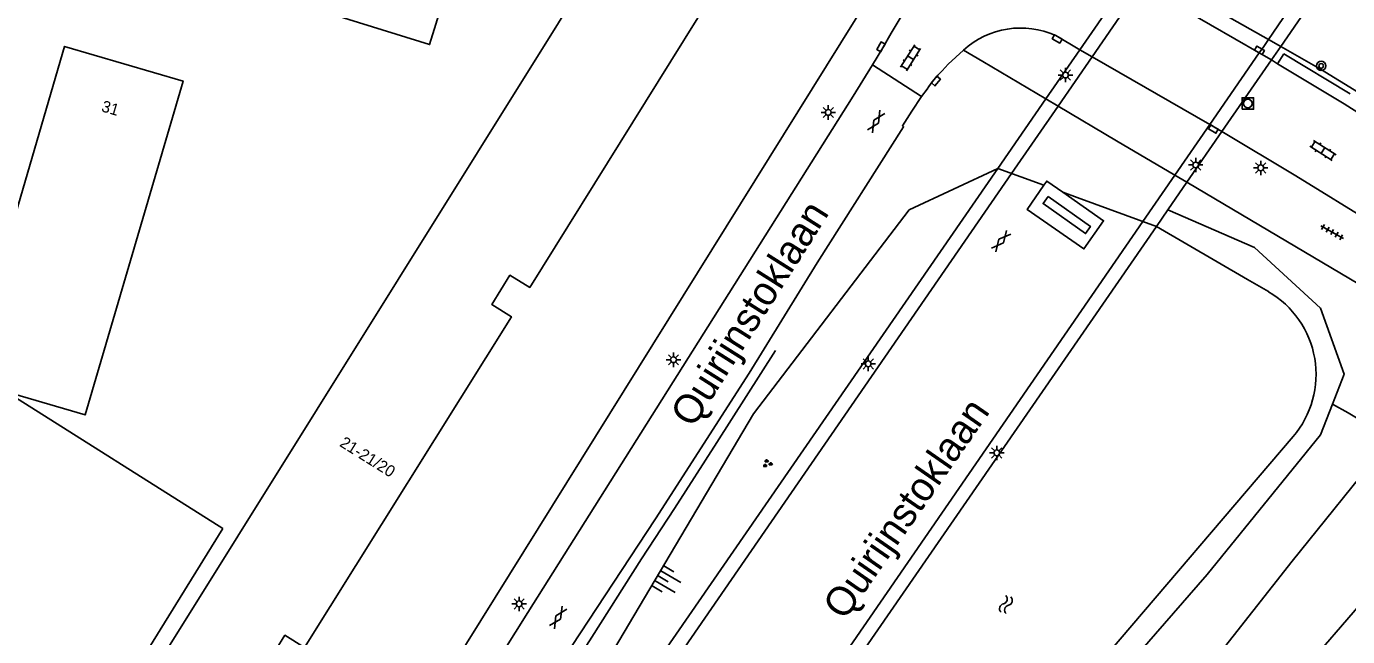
# Model space of a CAD drawing. Extents: x 132999 to 136000, y 398499 to 400501.
# Drawn here: x 134331.8 to 134446.1, y 398769 to 398821.9 of the extents above; entities that cross this region are included whole.
import ezdxf

# ---------------------------------------------------------------- set-up
doc = ezdxf.new("R2010")
doc.units = 0
for name, color, linetype in [('gg-afsc-hekwerk', 7, 'Continuous'), ('gg-anno-huisnummerreeks BGT', 7, 'Continuous'), ('gg-anno-openbare ruimte label', 7, 'Continuous'), ('gg-bbg-gedigitaliseerde bebouwing', 7, 'Continuous'), ('gg-bbg-gedigitaliseerde bijgebouw', 7, 'Continuous'), ('gg-bbg-hoofdgebouw', 7, 'Continuous'), ('gg-knt-BGT kruinlijn', 7, 'Continuous'), ('gg-knt-bovenkant onderkant talud', 7, 'Continuous'), ('gg-knt-bronhoudergrens', 7, 'Continuous'), ('gg-knt-verharding', 7, 'Continuous'), ('gg-knt-verharding nz', 7, 'Continuous'), ('gg-kwrk-kunstwerk', 7, 'Continuous'), ('gg-kwrk-kunstwerk niveau 01', 7, 'Continuous'), ('gt-grn-groengrens', 7, 'Continuous'), ('gt-knt-geleideconstructie', 7, 'Continuous'), ('gt-symb-boom', 7, 'Continuous'), ('gt-symb-gesloten verharding', 7, 'Continuous'), ('gt-symb-groenvak', 7, 'Continuous'), ('gt-symb-klinker verharding', 7, 'Continuous'), ('gt-symb-kolk', 7, 'Continuous'), ('gt-symb-lichtmast', 7, 'Continuous'), ('gt-symb-rioolschacht', 7, 'Continuous'), ('gt-symb-talud symbool', 7, 'Continuous'), ('gt-symb-tegel verharding', 7, 'Continuous'), ('gt-symb-watersymbool', 7, 'Continuous')]:
    doc.layers.add(name, color=color, linetype=linetype)

# ---------------------------------------------------------------- blocks, each defined once
blk = doc.blocks.new('gt0-TEG1')
at = {"layer": 'gt-symb-tegel verharding'}
for p, q in [((-1.12, 0), (1.12, 0)), ((-0.9, -0.25), (-0.9, 0.25)), ((-0.45, -0.25), (-0.45, 0.25)), ((0, -0.25), (0, 0.25)), ((0.45, -0.25), (0.45, 0.25)), ((0.9, -0.25), (0.9, 0.25))]:
    blk.add_line(p, q, dxfattribs=at)
blk = doc.blocks.new('gt0-LMAST')
at = {"layer": 'gt-symb-lichtmast'}
for p, q in [((-0.18, 0.17), (-0.45, 0.44)), ((-0.01, 0.25), (-0.01, 0.62)), ((0.17, 0.17), (0.44, 0.44)), ((-0.26, 0), (-0.63, 0)), ((-0.18, -0.18), (-0.45, -0.45)), ((-0.01, -0.25), (-0.01, -0.63)), ((0.44, -0.45), (0.17, -0.18)), ((0.24, 0), (0.62, 0))]:
    blk.add_line(p, q, dxfattribs=at)
blk.add_circle((-0.01, 0), 0.25, dxfattribs=at)
blk = doc.blocks.new('gt0-KL1')
at = {"layer": 'gt-symb-klinker verharding'}
for p, q in [((-1.15, 0.3), (1.15, 0.3)), ((-1, -0.3), (-1, 0.3)), ((-0.5, 0.3), (-0.5, 0.45)), ((0, -0.3), (0, 0.3)), ((0.5, 0.3), (0.5, 0.45)), ((1, -0.3), (1, 0.3)), ((-1.15, -0.3), (1.15, -0.3)), ((-0.5, -0.45), (-0.5, -0.3)), ((0.5, -0.45), (0.5, -0.3))]:
    blk.add_line(p, q, dxfattribs=at)
blk = doc.blocks.new('gt0-BOOM')
at = {"layer": 'gt-symb-boom'}
for radius in [0.4, 0.2]:
    blk.add_circle((0, 0), radius, dxfattribs=at)
blk = doc.blocks.new('gt0-KOLK')
at = {"layer": 'gt-symb-kolk'}
blk.add_lwpolyline([(0, 0), (0.37, 0), (0.37, 0.4), (-0.38, 0.4), (-0.38, 0), (0, 0)], dxfattribs=at)
blk = doc.blocks.new('gt0-GESVH1')
at = {"layer": 'gt-symb-gesloten verharding'}
for p, q in [((-0.99, -0.26), (0.01, 0.24)), ((0.01, -0.26), (-0.99, 0.24)), ((0.01, 0.24), (1.01, -0.26)), ((1.01, 0.24), (0.01, -0.26))]:
    blk.add_line(p, q, dxfattribs=at)
blk = doc.blocks.new('gt0-RS')
at = {"layer": 'gt-symb-rioolschacht'}
blk.add_lwpolyline([(-0.5, -0.5), (0.5, -0.5), (0.5, 0.5), (-0.5, 0.5)], close=True, dxfattribs=at)
blk.add_circle((0, 0), 0.375, dxfattribs=at)
blk = doc.blocks.new('gt0-WA')
at = {"layer": 'gt-symb-watersymbool'}
for centre, start, end in [((-0.32, 0.02), 28.0725, 151.9275), ((0.43, 0.42), 208.0725, 331.9275), ((-0.32, -0.43), 28.0725, 151.9275), ((0.43, -0.03), 208.0725, 331.9275)]:
    blk.add_arc(centre, 0.425, start, end, dxfattribs=at)
blk = doc.blocks.new('gt0-TALUD_1')
at = {"layer": 'gt-symb-talud symbool'}
for p, q in [((-1, -1), (-1, 0)), ((-0.5, -2), (-0.5, 0)), ((0, -1), (0, 0)), ((0.5, -2), (0.5, 0)), ((1, -1), (1, 0))]:
    blk.add_line(p, q, dxfattribs=at)
blk = doc.blocks.new('gt0-GRVAK')
at = {"layer": 'gt-symb-groenvak'}
for p, q in [((-0.11, 0.19), (-0.23, 0.24)), ((-0.18, 0.15), (0.09, 0.15)), ((-0.09, 0.21), (-0.16, 0.32)), ((-0.05, 0.21), (-0.05, 0.39)), ((0, 0.21), (0.06, 0.32)), ((0.01, 0.19), (0.13, 0.24)), ((0.26, -0.05), (0.2, 0.06)), ((0.3, -0.05), (0.3, 0.13)), ((0.35, -0.05), (0.41, 0.06)), ((-0.24, -0.23), (-0.36, -0.18)), ((-0.32, -0.26), (-0.05, -0.26)), ((-0.23, -0.21), (-0.29, -0.09)), ((-0.18, -0.2), (-0.18, -0.02)), ((-0.14, -0.21), (-0.07, -0.09)), ((-0.12, -0.23), (0, -0.18)), ((0.24, -0.07), (0.12, -0.02)), ((0.17, -0.11), (0.44, -0.11)), ((0.37, -0.07), (0.49, -0.02))]:
    blk.add_line(p, q, dxfattribs=at)

msp = doc.modelspace()

# ---------------------------------------------------------------- linework, layer by layer
at = {"layer": 'gg-afsc-hekwerk'}
for p, q in [((134362.12, 398755.98), (134404.98, 398824.83)), ((134419.99, 398815.58), (134414.54, 398818.81)), ((134421.05, 398814.96), (134419.99, 398815.58)), ((134426.1, 398811.96), (134421.05, 398814.96)), ((134431.15, 398808.97), (134426.1, 398811.96)), ((134432.19, 398808.36), (134431.15, 398808.97)), ((134453.08, 398795.98), (134432.19, 398808.36))]:
    msp.add_line(p, q, dxfattribs=at)
at = {"layer": 'gg-bbg-gedigitaliseerde bebouwing'}
for p in [(134330.09, 398790.22), (134307.47, 398711.69)]:
    msp.add_line(p, (134348.81, 398778.38), dxfattribs=at)
msp.add_lwpolyline([(134326.65, 398791.23), (134335.11, 398820.12), (134345.36, 398817.12), (134336.9, 398788.22), (134330.09, 398790.22)], dxfattribs=at)
at = {"layer": 'gg-bbg-gedigitaliseerde bijgebouw'}
msp.add_lwpolyline([(134369.98, 398830.88), (134366.68, 398820.29), (134338.4, 398829.08), (134341.7, 398839.67)], dxfattribs=at)
at = {"layer": 'gg-bbg-hoofdgebouw'}
msp.add_lwpolyline([(134384.77, 398833.13), (134384.69, 398833.18), (134308.48, 398711.06), (134316.99, 398705.79), (134334.84, 398734.45), (134333.18, 398735.48), (134334.75, 398738.01), (134336.43, 398736.96), (134354.3, 398765.58), (134352.62, 398766.62), (134354.17, 398769.15), (134355.87, 398768.09), (134373.77, 398796.73), (134372.07, 398797.79), (134373.64, 398800.32), (134375.35, 398799.26), (134393.18, 398827.9), (134384.77, 398833.13)], dxfattribs=at)
at = {"layer": 'gg-knt-BGT kruinlijn'}
msp.add_line((134431.61, 398753.84), (134447.13, 398771.76), dxfattribs=at)
at = {"layer": 'gg-knt-bovenkant onderkant talud'}
for p, q in [((134419.82, 398808.11), (134415.84, 398809.57)), ((134421.46, 398807.51), (134422.71, 398807.05)), ((134422.71, 398807.05), (134429.55, 398804.54)), ((134429.55, 398804.54), (134437.44, 398799.95)), ((134441.37, 398786.35), (134398.31, 398735.92))]:
    msp.add_line(p, q, dxfattribs=at)
for points in [[(134394.7, 398788.32), (134408.18, 398805.98), (134415.84, 398809.57)], [(134394.7, 398788.32), (134361.07, 398731.46), (134357.46, 398726.15)]]:
    msp.add_lwpolyline(points, dxfattribs=at)
at = {"layer": 'gg-knt-bronhoudergrens'}
for p, q in [((134439.24, 398820.73), (134429.59, 398826.2)), ((134440.31, 398820.12), (134439.24, 398820.73)), ((134440.31, 398820.12), (134443.74, 398818.17)), ((134443.74, 398818.17), (134464.15, 398805.53))]:
    msp.add_line(p, q, dxfattribs=at)
at = {"layer": 'gg-knt-verharding'}
for p, q in [((134420.85, 398821.07), (134422.93, 398819.83)), ((134412.86, 398819.8), (134414.54, 398818.81)), ((134440.03, 398818.63), (134439.5, 398818.95)), ((134405.01, 398818.53), (134409.23, 398815.78)), ((134445.79, 398815.16), (134440.03, 398818.63)), ((134409.23, 398815.78), (134409.72, 398816.43)), ((134439.24, 398798.9), (134437.44, 398799.95))]:
    msp.add_line(p, q, dxfattribs=at)
for points in [[(134407.7, 398823.11), (134407.65, 398822.99), (134406.61, 398821.26), (134405.9, 398820), (134405.01, 398818.53)], [(134412.86, 398819.8), (134411.54, 398818.6), (134411.01, 398818)], [(134405.01, 398818.53), (134403.33, 398815.81), (134375.19, 398771.11), (134361.88, 398749.9), (134349.42, 398730.18), (134344.08, 398721.69)], [(134353.64, 398729.08), (134363.55, 398744.49), (134369.29, 398753.34), (134371.99, 398757.42), (134378.23, 398767.08), (134386.22, 398779.22), (134394.34, 398791.85), (134400.21, 398801.38), (134407.68, 398813.17), (134407.59, 398813.26), (134408.4, 398814.53), (134409.23, 398815.78)], [(134445.79, 398815.16), (134475.62, 398796.2), (134477.69, 398794.78)], [(134448.83, 398804.4), (134448.45, 398804.7), (134441.61, 398808.91), (134435.22, 398812.75)], [(134406.95, 398731.89), (134441.3, 398775.57), (134449.33, 398785.56)]]:
    msp.add_lwpolyline(points, dxfattribs=at)
for centre, radius, start, end in [((134417.82, 398814.33), 7.39, 65.8059, 132.1894), ((134418.13, 398810.84), 10.1, 134.8423, 146.3438), ((134435.07, 398791.73), 8.29, 319.5036, 59.7955)]:
    msp.add_arc(centre, radius, start, end, dxfattribs=at)
at = {"layer": 'gg-knt-verharding nz'}
for p, q in [((134428.78, 398825.14), (134438.45, 398819.57)), ((134422.93, 398819.83), (134423.99, 398819.22)), ((134434.18, 398813.37), (134423.99, 398819.22)), ((134439.5, 398818.95), (134438.45, 398819.57)), ((134435.22, 398812.75), (134434.18, 398813.37))]:
    msp.add_line(p, q, dxfattribs=at)
at = {"layer": 'gg-kwrk-kunstwerk'}
for points in [[(134421.46, 398807.51), (134424.99, 398805.04), (134423.28, 398802.59), (134418.36, 398806.02), (134419.82, 398808.11)], [(134421.46, 398807.51), (134420.07, 398808.47), (134419.82, 398808.11)], [(134420.18, 398807.13), (134419.75, 398806.52), (134423.42, 398803.93), (134423.85, 398804.54), (134420.18, 398807.13)]]:
    msp.add_lwpolyline(points, dxfattribs=at)
at = {"layer": 'gg-kwrk-kunstwerk niveau 01'}
for p, q in [((134422.93, 398819.83), (134427.21, 398826.04)), ((134423.99, 398819.22), (134428.27, 398825.43)), ((134439.24, 398820.73), (134441.36, 398823.8)), ((134440.31, 398820.12), (134442.35, 398823.09)), ((134438.45, 398819.57), (134438.84, 398820.13)), ((134438.84, 398820.13), (134439.24, 398820.73)), ((134439.9, 398819.53), (134440.31, 398820.12)), ((134422.93, 398819.83), (134419.99, 398815.58)), ((134423.99, 398819.22), (134421.05, 398814.96)), ((134434.18, 398813.37), (134438.45, 398819.57)), ((134435.22, 398812.75), (134439.5, 398818.95)), ((134439.5, 398818.95), (134439.9, 398819.53)), ((134415.84, 398809.57), (134419.99, 398815.58)), ((134417.03, 398809.13), (134421.05, 398814.96)), ((134434.18, 398813.37), (134431.15, 398808.97)), ((134435.22, 398812.75), (134432.19, 398808.36)), ((134363.68, 398733.98), (134415.84, 398809.57)), ((134364.71, 398733.27), (134417.03, 398809.13)), ((134428.39, 398804.97), (134431.15, 398808.97)), ((134430.54, 398805.97), (134432.19, 398808.36)), ((134429.55, 398804.54), (134430.54, 398805.97)), ((134374.35, 398726.55), (134428.39, 398804.97)), ((134379.35, 398731.83), (134429.55, 398804.54))]:
    msp.add_line(p, q, dxfattribs=at)
at = {"layer": 'gt-grn-groengrens'}
for p, q in [((134440.56, 398819.48), (134440.03, 398818.63)), ((134446.32, 398816.01), (134440.56, 398819.48))]:
    msp.add_line(p, q, dxfattribs=at)
for points in [[(134430.54, 398805.97), (134438.04, 398802.71), (134443.74, 398797.46), (134445.79, 398791.76), (134444.78, 398789.16)], [(134444.78, 398789.16), (134443.74, 398786.51), (134433.93, 398774.42), (134397.43, 398732.45), (134390.82, 398729.48), (134385.8, 398729.48), (134379.87, 398729.94), (134372.8, 398718.99), (134369.05, 398712.04)], [(134449.83, 398786.18), (134446.13, 398788.4), (134444.78, 398789.16)]]:
    msp.add_lwpolyline(points, dxfattribs=at)
at = {"layer": 'gt-knt-geleideconstructie'}
msp.add_lwpolyline([(134396.6, 398793.81), (134391.52, 398785.85), (134387.86, 398780.12), (134385.02, 398775.76), (134380.73, 398768.99), (134377.15, 398763.41), (134373.51, 398757.8), (134370.62, 398753.28), (134367.74, 398748.79), (134364.26, 398743.18), (134358.21, 398733.85)], dxfattribs=at)

# ---------------------------------------------------------------- block references
at = {"layer": 'gt-symb-boom'}
msp.add_blockref('gt0-BOOM', (134443.8, 398818.44), dxfattribs=at)
at = {"layer": 'gt-symb-gesloten verharding'}
for p, rotation in [((134405.3, 398813.61), 58.20108717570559), ((134416.11, 398803.27), 49.38006045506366), ((134377.8, 398770.69), 57.37496440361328)]:
    msp.add_blockref('gt0-GESVH1', p, dxfattribs=dict(at, rotation=rotation))
at = {"layer": 'gt-symb-groenvak'}
msp.add_blockref('gt0-GRVAK', (134395.89, 398784.01), dxfattribs=at)
at = {"layer": 'gt-symb-klinker verharding'}
for p, rotation in [((134408.29, 398819.14), 57.70905164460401), ((134443.96, 398811.12), 147.37496440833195)]:
    msp.add_blockref('gt0-KL1', p, dxfattribs=dict(at, rotation=rotation))
at = {"layer": 'gt-symb-kolk'}
for p, rotation in [((134421.06, 398820.95), 149.9209741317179), ((134405.9, 398820), 60.66720921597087), ((134438.37, 398819.61), -30.590435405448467), ((134410.32, 398817.25), -129.40224128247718), ((134434.57, 398813.14), 150.12717895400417)]:
    msp.add_blockref('gt0-KOLK', p, dxfattribs=dict(at, rotation=rotation))
at = {"layer": 'gt-symb-lichtmast'}
for p in [(134421.69, 398817.65), (134401.18, 398814.41), (134432.96, 398809.86), (134438.58, 398809.61), (134387.79, 398793), (134404.64, 398792.65), (134415.75, 398784.94), (134374.44, 398771.87)]:
    msp.add_blockref('gt0-LMAST', p, dxfattribs=at)
at = {"layer": 'gt-symb-rioolschacht'}
msp.add_blockref('gt0-RS', (134437.46, 398815.18), dxfattribs=at)
at = {"layer": 'gt-symb-talud symbool', "xscale": 0.9999779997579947, "yscale": 0.9999779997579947, "rotation": 59.99927221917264}
msp.add_blockref('gt0-TALUD_1', (134386.45, 398774.29), dxfattribs=at)
at = {"layer": 'gt-symb-tegel verharding', "rotation": 150.20538279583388}
msp.add_blockref('gt0-TEG1', (134444.75, 398804.05), dxfattribs=at)
at = {"layer": 'gt-symb-watersymbool', "rotation": -105.7172524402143}
msp.add_blockref('gt0-WA', (134416.55, 398771.86), dxfattribs=at)

# ---------------------------------------------------------------- texts
at = {"layer": 'gg-anno-huisnummerreeks BGT'}
for s, rotation, p in [('31', 343.7, (134338.23, 398814.52)), ('21-21/20', 328, (134358.83, 398785.57))]:
    msp.add_text(s, height=1, rotation=rotation, dxfattribs=at).set_placement(p)
at = {"layer": 'gg-anno-openbare ruimte label'}
for rotation, p in [(57.7, (134389.49, 398787.02)), (55.2, (134402.6, 398770.36))]:
    msp.add_text('Quirijnstoklaan', height=2.5, rotation=rotation, dxfattribs=at).set_placement(p)

doc.saveas('drawing.dxf')
